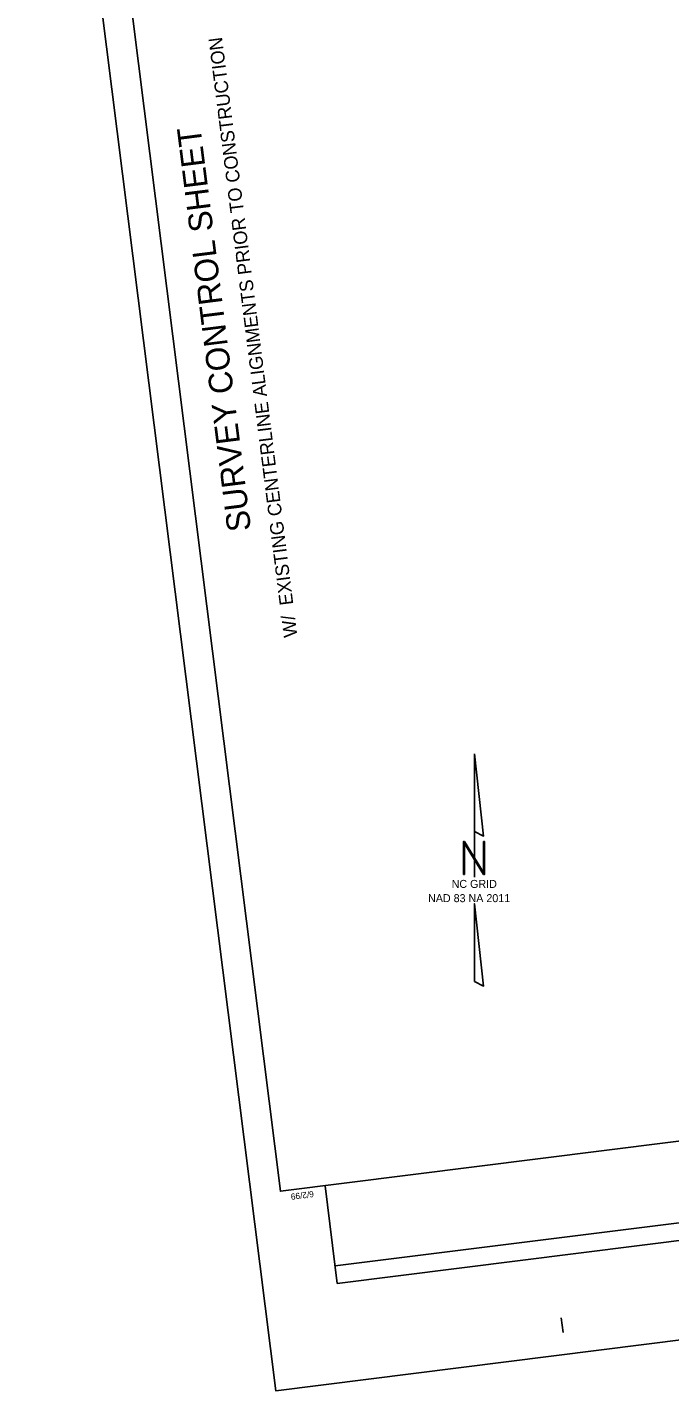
# Model space of a CAD drawing. Extents: x 476627 to 479509, y 495837 to 499842.
# Drawn here: x 476627 to 477831, y 495837 to 498393 of the extents above; entities that cross this region are included whole.
import ezdxf

# ---------------------------------------------------------------- set-up
doc = ezdxf.new("R2010")
doc.units = 0
for name, color, linetype in [('CTL North Arrow NAD 83 NA 2011 CELL', 7, 'Continuous'), ('CTL Sheet Border CELL', 7, 'Continuous'), ('Sheet Block Revision CELL', 7, 'Continuous'), ('Sheet Plot Border Outside CELL', 7, 'Continuous')]:
    doc.layers.add(name, color=color, linetype=linetype)

msp = doc.modelspace()

# ---------------------------------------------------------------- linework, layer by layer
at = {"layer": 'CTL North Arrow NAD 83 NA 2011 CELL'}
msp.add_line((477465.2, 496813.2), (477465.2, 496813.2), dxfattribs=at)
for points in [[(477464.8, 497031.4), (477464.8, 496885.6), (477482, 496877)], [(477444.2, 496805), (477445.9, 496805), (477445.9, 496863.3), (477482, 496805), (477483.7, 496805), (477483.7, 496866.7), (477482, 496866.7), (477482, 496808.4), (477445.9, 496866.7), (477444.2, 496866.7)], [(477464.8, 496604.3), (477482, 496595.8), (477464.8, 496750.1)]]:
    msp.add_lwpolyline(points, close=True, dxfattribs=at)
msp.add_lwpolyline([(477464.8, 496885.6), (477464.8, 496799.8)], dxfattribs=at)
at = {"layer": 'CTL Sheet Border CELL'}
msp.add_line((477631, 495946.3), (477627.6, 495973.8), dxfattribs=at)
msp.add_lwpolyline([(476686.3, 499507.1), (477101.1, 496211.1), (479408.3, 496501.4), (478993.5, 499797.5)], close=True, dxfattribs=at)
at = {"layer": 'Sheet Block Revision CELL'}
for p, q in [((478940.5, 496289.6), (477203.7, 496071.1)), ((478944.7, 496256.7), (477207.8, 496038.1)), ((477207.8, 496038.1), (477184.7, 496221.6))]:
    msp.add_line(p, q, dxfattribs=at)
at = {"layer": 'Sheet Plot Border Outside CELL'}
msp.add_lwpolyline([(479509.4, 496141.4), (479043.7, 499841.7), (476626.7, 499537.6), (477092.3, 495837.2)], close=True, dxfattribs=at)

# ---------------------------------------------------------------- texts
at = {"layer": 'CTL North Arrow NAD 83 NA 2011 CELL'}
for s, p in [('NC GRID', (477422.1, 496779.8)), ('NAD 83 NA 2011', (477377.9, 496753.1))]:
    msp.add_text(s, height=15, rotation=360, dxfattribs=at).set_placement(p)
at = {"layer": 'CTL Sheet Border CELL'}
for s, height, rotation, p in [('W/  EXISTING CENTERLINE ALIGNMENTS PRIOR TO CONSTRUCTION', 25.469, 97.1725, (477133, 497251.2)), ('SURVEY CONTROL SHEET ', 44.294, 97.1725, (477046.3, 497450.7)), ('6/2/99', 11.63, 187.1725, (477162.9, 496211.9))]:
    msp.add_text(s, height=height, rotation=rotation, dxfattribs=at).set_placement(p)

doc.saveas('drawing.dxf')
